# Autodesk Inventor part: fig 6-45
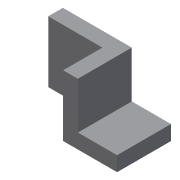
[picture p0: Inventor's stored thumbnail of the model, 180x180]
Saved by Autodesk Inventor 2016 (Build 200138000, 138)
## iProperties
Shininess: 77.0
Angle Display Precision: 2
Document Length Units: 11269
Document Angle Units: 11279
Document Time Units: 11290
Document Mass Units: 11283
Document Length Units Precision: 3
Document Angle Units Precision: 2
Created: 2001-12
Part Number: fig 6-45
Document SubType Name: Modeling
Designer: Renu Muthoo
Density: 1 g/cm^3
Material: Generic
Appearance: Default
Density: 0.0
Volumn: 0.0
Area: 0.0
PropertySet Name: Model Information
Control State: 0
Master: False
Checked Out: False
Author: Renu Muthoo
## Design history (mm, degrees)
node "Sketch1"
sketch "Sketch2"
  geometry: L1 (16.794, 27.142)-(16.794, -22.858); L2 (16.794, -22.858)-(-27.206, -22.858); L3 (-27.206, -22.858)-(-27.206, -10.858); L4 (-27.206, -10.858)-(4.794, -10.858); L5 (4.794, -10.858)-(4.794, 27.142); L6 (4.794, 27.142)-(16.794, 27.142)
  constraints: 12 end point, 4 parallel, 2 perpendicular, 1 vertical
  dimensions: "d0" = 44 distance of L1.end L2.end; "d1" = 50 distance of L1.start L1.end; "d2" = 12 distance of L2.end L3.end
extrude "Extrusion1" new body sketch "Sketch2" distance "d3" = 44; taper "d4" = 0 deg
sketch "Sketch4"
  geometry: L1 (-16.794, -27.142)-(-16.794, 22.858) reference; L2 (27.206, 22.858)-(27.206, 10.858) reference; L3 (-16.794, -27.142)-(-61.001, -27.142); L4 (-61.001, -27.142)-(-61.001, 22.858); L5 (-61.001, 22.858)-(-16.794, 22.858)
  constraints: 6 end point, 2 perpendicular, 1 parallel
extrude "Extrusion3" join sketch "Sketch4" distance "d13" = 12; taper "d14" = 0 deg
body "Solid1"
